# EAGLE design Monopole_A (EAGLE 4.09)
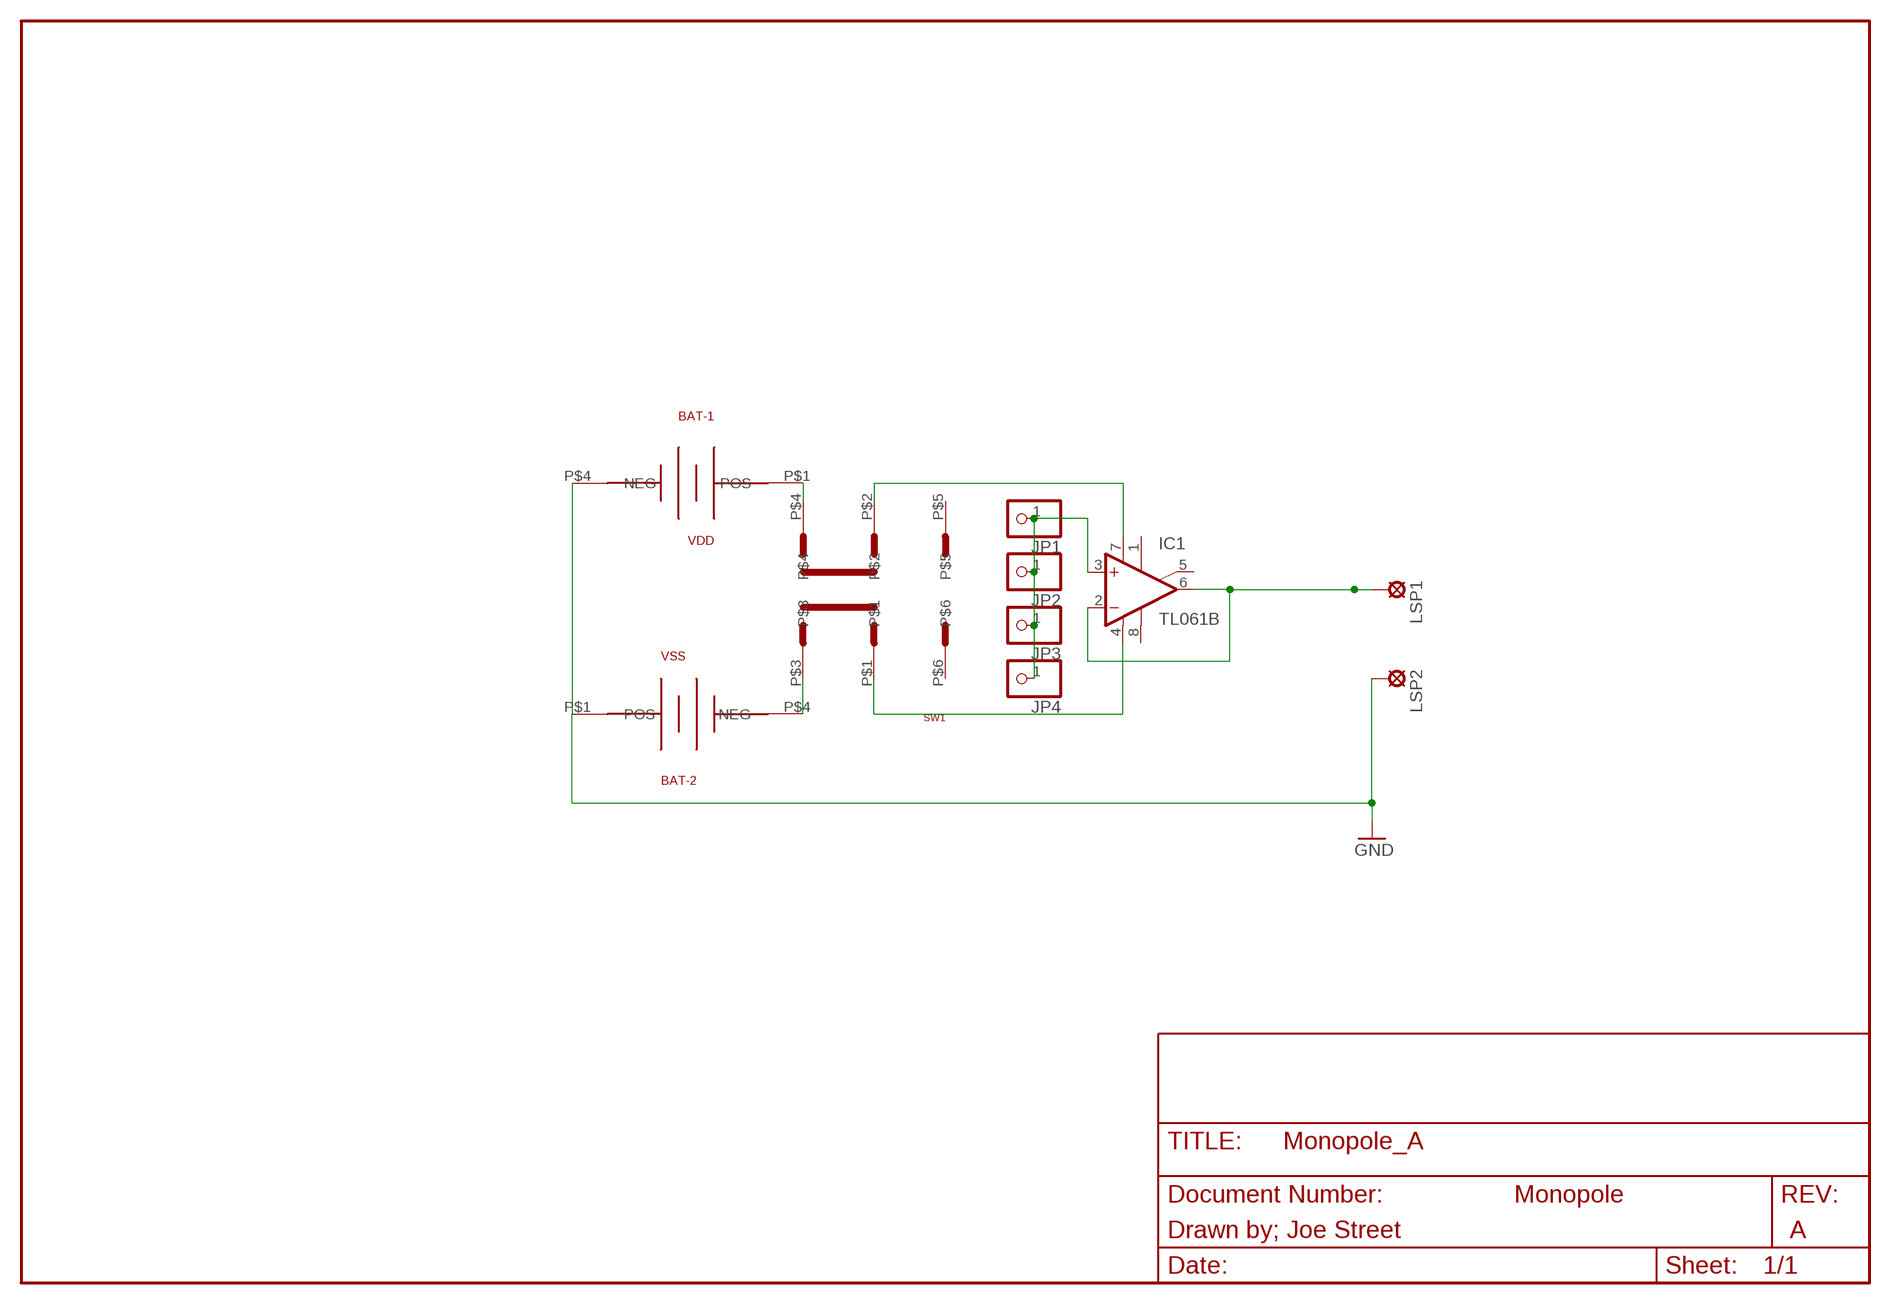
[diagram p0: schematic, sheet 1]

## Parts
IC1  TL061B  [SO08]
JP1  PINHD-1X1  [1X01]
JP2  PINHD-1X1  [1X01]
JP3  PINHD-1X1  [1X01]
JP4  PINHD-1X1  [1X01]
LSP1  LSP10  [LSP10]
LSP2  LSP10  [LSP10]
SW1  SW  [AYZ0202T]
VDD  BAT-1  [BR-T]
VSS  BAT-2  [BR-B]

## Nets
GND: LSP2.MP VDD.P$4(NEG) VSS.P$1(POS)
IN+: IC1.3(+IN) JP1.1 JP2.1 JP3.1 JP4.1
N$2: SW1.P$4 VDD.P$1(POS)
N$3: IC1.2(-IN) IC1.6(OUT) LSP1.MP
N$4: SW1.P$3 VSS.P$4(NEG)
V+: IC1.7(V+) SW1.P$2
V-: IC1.4(V-) SW1.P$1
Unconnected: IC1.1(ON1) IC1.5(ON2) IC1.8(OPT) SW1.P$5 SW1.P$6

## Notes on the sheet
- Monopole
- Drawn by; Joe Street | A

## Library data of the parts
IC1 = MY_linear:TL061: OP AMP
JP1-JP4 = pinhead:PINHD-1X1: PIN HEADER
LSP1 LSP2 = solpad:LSP10: SOLDER PAD
SW1 = ITT-cannon:SW: SMD DPDT SLIDE SWITCH
VDD = keystone:BAT-1
VSS = keystone_b:BAT-2

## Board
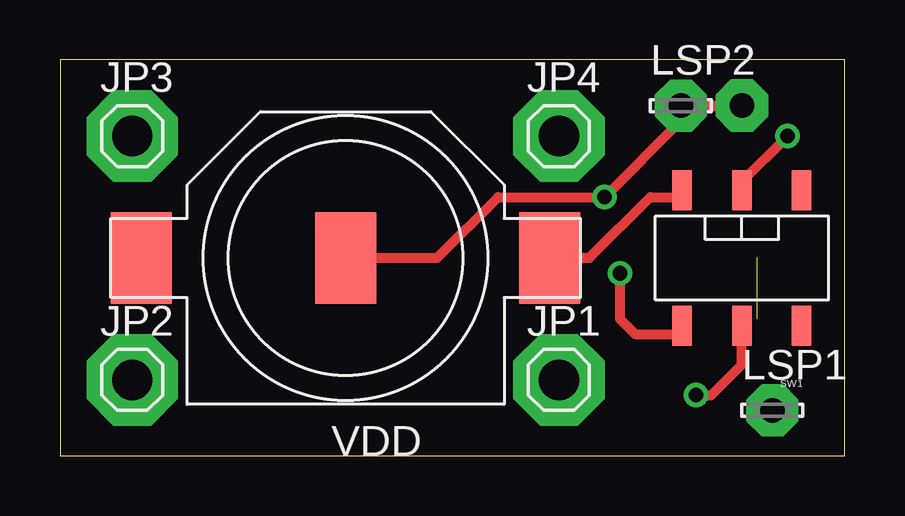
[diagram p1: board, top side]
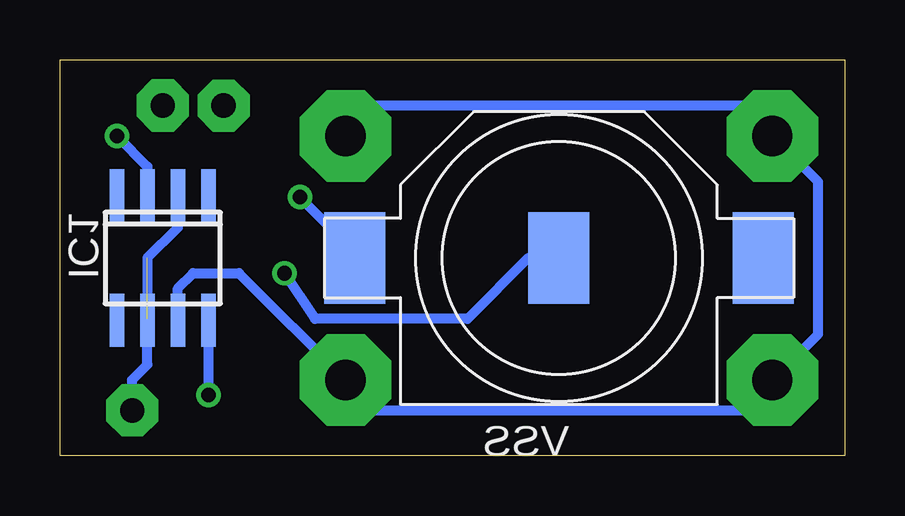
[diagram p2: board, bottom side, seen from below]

Size 32.69 x 16.5 mm. Coordinates in mm from the lower left corner, seen from the top.
Outline: 0,0 32.69,0 32.69,16.5 0,16.5 0,0
Copper layers used: Top, Bottom

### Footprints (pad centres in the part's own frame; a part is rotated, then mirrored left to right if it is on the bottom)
SO08 = smd 0.6 x 2.2 bottom: 1 -1.905,2.6; 2 -0.635,2.6; 3 0.635,2.6; 4 1.905,2.6; 5 1.905,-2.6; 6 0.635,-2.6; 7 -0.635,-2.6; 8 -1.905,-2.6
1X01 = drill 1.676 pad 3.81 octagon: 1 0,0
LSP10 = drill 1.016 pad 2.159 octagon: MP 0,0
AYZ0202T = smd 0.813 x 1.676: P$1 0,2.819; P$2 0,-2.819; P$3 2.489,2.819; P$4 2.489,-2.819; P$5 -2.489,-2.819; P$6 -2.489,2.819
BR-T = smd 2.54 x 1.27: P$1 -8.509,0; P$2 -8.509,1.27; P$3 -8.509,-1.27; P$4 0,0; P$5 0,1.27; P$6 0,-1.27; P$7 8.509,0; P$8 8.509,1.27; P$9 8.509,-1.27
BR-B = smd 2.54 x 1.27 bottom: P$1 -8.509,0; P$2 -8.509,1.27; P$3 -8.509,-1.27; P$4 0,0; P$5 0,1.27; P$6 0,-1.27; P$7 8.509,0; P$8 8.509,1.27; P$9 8.509,-1.27

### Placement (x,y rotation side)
IC1  28.41,8.25 180 top
JP1  20.79,3.17 0 top
JP2  3.01,3.17 0 top
JP3  3.01,13.33 0 top
JP4  20.79,13.33 0 top
LSP1  29.68,1.9 0 top
LSP2  25.87,14.6 0 top
SW1  28.41,8.25 180 top
VDD  11.9,8.25 180 top
VSS  11.9,8.25 180 top

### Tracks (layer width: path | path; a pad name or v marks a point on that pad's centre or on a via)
GND  (via drill 0.61 pad 1.02, 1.02 pad 2.18)
  Top 0.406: VDD.P$4 15.71,8.25 18.25,10.79 v22.7,10.79 25.87,13.97 LSP2.MP v28.41,14.6
  Bottom 0.406: VSS.P$1 20.15,8.25 v22.7,10.79
IN+
  Bottom 0.406: IC1.3 27.77,6.98 27.14,7.62 25.23,7.62 JP1.1 19.52,1.9 4.28,1.9 JP2.1 1.1,5.08 1.1,11.43 JP3.1 4.28,14.6 19.52,14.6 JP4.1
N$2
  Top 0.406: VDD.P$1 22.06,8.25 24.6,10.79 25.87,10.79 25.92,10.84 SW1.P$4
N$3  (1 unrouted)
  Bottom 0.406: LSP1.MP 29.68,3.17 29.04,3.8 IC1.2 29.04,5.71 29.04,8.25 27.77,9.52 IC1.6
N$4  (via drill 0.61 pad 1.02)
  Top 0.406: v23.33,7.62 23.33,5.71 23.96,5.08 25.87,5.08 25.92,5.13 SW1.P$3
  Bottom 0.406: VSS.P$4 13.17,8.25 15.71,5.71 22.06,5.71 v23.33,7.62
V+  (via drill 0.61 pad 1.02)
  Top 0.406: SW1.P$2 28.41,11.43 v30.31,13.33
  Bottom 0.406: v30.31,13.33 29.04,12.06 IC1.7 29.04,10.79
V-  (via drill 0.61 pad 1.02)
  Top 0.406: v26.5,2.54 27.14,2.54 28.41,3.8 SW1.P$1
  Bottom 0.406: IC1.4 v26.5,2.54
